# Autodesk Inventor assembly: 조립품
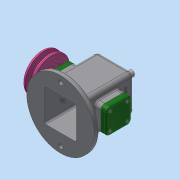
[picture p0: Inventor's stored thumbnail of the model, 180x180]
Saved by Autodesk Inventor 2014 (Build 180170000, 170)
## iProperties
Created: 2021-08
Part Number: 조립품
Document SubType Name: Assembly
Designer: dg
Author: dg
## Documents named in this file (16)
- C:\Users\dg\Desktop\710806V1013\조립품.iam
- C:\Users\dg\Desktop\710806V1013\본체.ipt
- C:\Users\dg\Desktop\710806V1013\V벨트풀리.ipt
- C:\Users\dg\Desktop\710806V1013\고정핀 1.2x8.ipt
- C:\Users\dg\Desktop\710806V1013\뒤커버.ipt
- C:\Users\dg\Desktop\710806V1013\링크.ipt
- C:\Users\dg\Desktop\710806V1013\멈춤나사 M3x8.ipt
- C:\Users\dg\Desktop\710806V1013\베어링 12x32x10.ipt
- C:\Users\dg\Desktop\710806V1013\볼트 M4.ipt
- C:\Users\dg\Desktop\710806V1013\부시.ipt
- C:\Users\dg\Desktop\710806V1013\슬라이드.ipt
- C:\Users\dg\Desktop\710806V1013\앞커버.ipt
- C:\Users\dg\Desktop\710806V1013\오일 실 12 25 7.ipt
- C:\Users\dg\Desktop\710806V1013\키 4x4x10.ipt
- C:\Users\dg\Desktop\710806V1013\편심축.ipt
- C:\Users\dg\Desktop\710806V1013\핀 5x18.ipt
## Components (3 placed, 3 different names)
1. V벨트풀리:1
2. 핀 5x18:1
3. 고정핀 1.2x8:2
## Component patterns: 구성요소 패턴 1:2 (4 elements), 구성요소 패턴 1:3 (4 elements), 구성요소 패턴 1:4 (4 elements)
